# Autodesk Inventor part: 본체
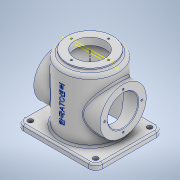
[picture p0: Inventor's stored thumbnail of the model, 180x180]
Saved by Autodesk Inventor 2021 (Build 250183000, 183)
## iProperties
Created: 2021-02
Part Number: 본체
Material: 알루미늄 6061
Document SubType Name: Modeling
Designer: mdu2-97
Density: 2.7 g/cm^3
Appearance: 알루미늄 - 평지
Mass: 1234.41 g
Surface Area: 1072.03 cm^2
Volume: 457.188 cm^3
Author: mdu2-97
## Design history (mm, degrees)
sketch "스케치1"
  geometry: C1 r 50 at (0, 0); 1 further point
  constraints: 1 centre point, 1 coincident
  dimensions: "d0" = 100 diameter of C1
extrude "돌출1" new body sketch "스케치1" distance "d1" = 110; taper "d2" = 0 deg
sketch "스케치2"
  geometry: C1 r 41 at (0, 0); 1 further point
  constraints: 1 centre point, 1 coincident
  dimensions: "d3" = 82 diameter of C1
extrude "돌출2" join sketch "스케치2" distance "d4" = 5; taper "d5" = 0 deg
sketch "스케치3"
  geometry: L1 (50, 110)-(-50, 110) reference; L2 (50, 0)-(-50, 0) reference; 1 further point
  node "투영된 루프1"
sketch "스케치5"
  geometry: L1 (41, 115)-(-41, 115) reference; L2 (0, 115)-(0, 0); L3 (50, 0)-(-50, 0) reference
  constraints: 2 end point, 1 midpoint, 1 perpendicular
node "작업 평면1"
sketch "스케치6"
  geometry: L1 (119.427, 0)-(-19.427, 0); C1 r 41 at (50, 0); 2 further points
  constraints: 2 end point, 1 centre point, 1 coincident, 1 horizontal, 1 midpoint
  dimensions: "d14" = 82 diameter of C1; "d15" = 50 distance of point (0, 0) C1.centre
extrude "돌출3" join sketch "스케치6" extent not by distance; stored distance "d16" = 0; taper "d17" = 0 deg
sketch "스케치7"
  geometry: C1 r 27 at (0, 0); 1 further point
  constraints: 1 centre point
  dimensions: "d18" = 54 diameter of C1
extrude "돌출4" cut sketch "스케치7" extent not by distance; stored distance "d19" = 0; taper "d20" = 0 deg
sketch "스케치8"
  geometry: C1 r 50 at (0, 0) reference; 1 further point
sketch "스케치9"
  geometry: L1 (-70, -60)-(70, -60); L2 (70, -60)-(70, 60); L3 (70, 60)-(-70, 60); L4 (-70, 60)-(-70, -60); L5 (-70, -60)-(70, 60); L6 (70, -60)-(-70, 60); 1 further point
  constraints: 12 end point, 2 midpoint, 2 parallel, 1 horizontal, 1 perpendicular
  dimensions: "d21" = 140 distance of L3.end L2.end; "d22" = 120 distance of L2.end L1.end
extrude "돌출5" join sketch "스케치9" distance "d23" = 10; taper "d24" = 0 deg
sketch "스케치10"
  geometry: C1 r 50 at (0, 0) reference; 1 further point
hole "구멍2" sketch "스케치10" at (0, 0) diameter "d25" = 54; stored, may be unused: countersink angle "d29" = 90 deg, drill point angle "d31" = 0 deg; dims "d26" = 7, "d27" = 84, "d28" = 112, "d30" = 112
sketch "스케치11"
  geometry: C1 r 27 at (0, 0) reference; C2 r 27 at (0, 0) reference; C3 r 41 at (0, 0) reference; 2 further points
  dimensions: "d32" = 33 distance of point (0, 33) C1.centre
hole "구멍3" sketch "스케치11" at (0, 33) diameter "d33" = 3.242; stored, may be unused: countersink angle "d37" = 90 deg, drill point angle "d39" = 118 deg; dims "d34" = 8, "d35" = 84, "d36" = 112, "d38" = 10
sketch "스케치12"
  geometry: 2 further points
  dimensions: "d43" = 33 distance of point (0, 33) point (0, 0)
hole "구멍4" sketch "스케치12" at (0, 33) diameter "d44" = 3.242; stored, may be unused: countersink angle "d48" = 90 deg, drill point angle "d50" = 118 deg; dims "d45" = 8, "d46" = 84, "d47" = 112, "d49" = 10
fillet "모깎기1" dims "d63" = 6
chamfer "모따기1" distance "d64" = 1; stored, may be unused: second distance "d65" = 2, angle "d66" = 45 deg
fillet "모깎기2" dims "d67" = 3
fillet "모깎기3" dims "d68" = 12
sketch "스케치14"
  geometry: A1 r 12 centre (-58, 48) between (-58, 60) and (-70, 48) reference; A2 r 12 centre (58, 48) between (70, 48) and (58, 60) reference; A3 r 12 centre (58, -48) between (58, -60) and (70, -48) reference; A4 r 12 centre (-58, -48) between (-70, -48) and (-58, -60) reference; 1 further point
hole "구멍6" sketch "스케치14" at (58, -48), (58, 48), (-58, -48), (-58, 48) diameter "d69" = 9; stored, may be unused: countersink angle "d73" = 90 deg, drill point angle "d75" = 0 deg; dims "d70" = 8, "d71" = 84, "d72" = 112, "d74" = 10
fillet "모깎기4" dims "d76" = 3
fillet "모깎기5" dims "d77" = 3
node "작업 평면2"
sketch "스케치15"
  geometry: L1 (58, -10)-(-58, -10) reference; 2 further points
  constraints: 1 vertical alignment, 1 other
  dimensions: "d79" = 66 distance from line of L1 point (0, 56)
feature "엠보싱1" sketch "스케치15" dims "d16" = 0, "d80" = 0.5, "d81" = 0
node "솔리드1"
mirror "미러1"
pattern_circular "원형 패턴1" dims angle "d41" = 360 deg
mirror "미러2"
pattern_circular "원형 패턴2" dims angle "d52" = 360 deg
node "투영된 루프2"
feature "A9D066F2-1C7D-4E18-AEED-F7BC21143FA4" dims "d25" = 54, "d26" = 7, "d27" = 84, "d28" = 112, "d29" = 90 deg, "d30" = 112, "d31" = 0
other parameters: "d13" = 59, "d78" = 57.75
